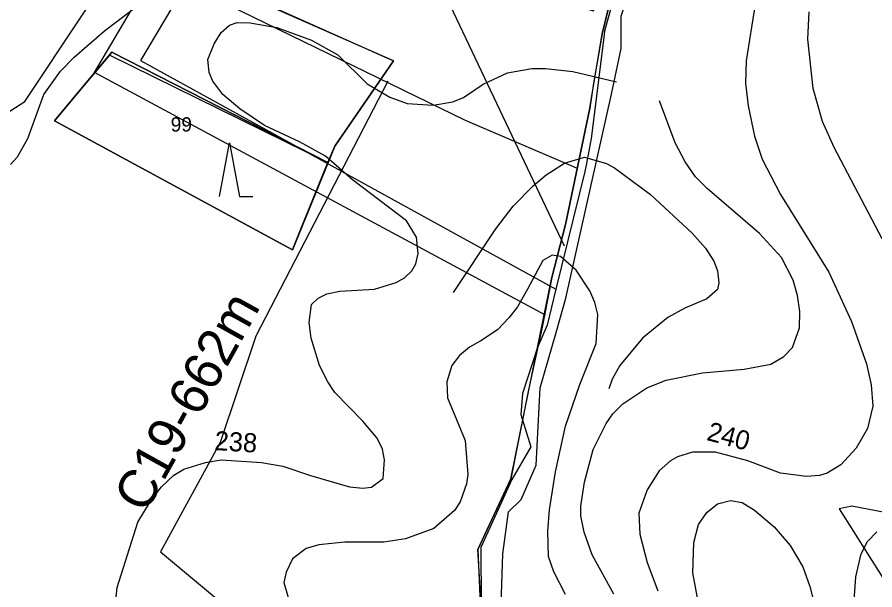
# Model space of a CAD drawing. Extents: x -662500 to -655523, y -1056000 to -1049993.
# Drawn here: x -659685.9 to -659235.8, y -1052866.9 to -1052566.6 of the extents above; entities that cross this region are included whole.
import ezdxf

# ---------------------------------------------------------------- set-up
doc = ezdxf.new("R2010")
doc.units = 0
for name, color, linetype in [('58', 7, 'Continuous'), ('Vrstva 1', 7, 'Continuous'), ('Vrstva 12', 7, 'Continuous'), ('Vrstva 15', 7, 'Continuous'), ('Vrstva 16', 7, 'Continuous'), ('Vrstva 24', 7, 'Continuous'), ('Vrstva 37', 7, 'Continuous'), ('Vrstva 5', 7, 'Continuous'), ('Vrstva 51', 7, 'Continuous'), ('Vrstva 57', 7, 'Continuous'), ('Vrstva 7', 7, 'Continuous')]:
    doc.layers.add(name, color=color, linetype=linetype)

msp = doc.modelspace()

# ---------------------------------------------------------------- linework, layer by layer
at = {"layer": '58'}
msp.add_lwpolyline([(-659328.02, -1052300.49), (-659306.01, -1052350.14), (-659351.19, -1052345.64), (-659376.51, -1052386.45), (-659386.77, -1052453.16), (-659389.91, -1052477.37), (-659350.86, -1052466.04), (-659360.95, -1052515.07), (-659372.04, -1052553.55), (-659377.67, -1052573.87), (-659378, -1052577.29), (-659384.78, -1052630.2), (-659387.27, -1052644.16), (-659388.08, -1052647.48), (-659403.17, -1052709.23), (-659407.79, -1052728.1), (-659412.92, -1052739.74), (-659420.7, -1052763.94), (-659421.56, -1052774.88), (-659416.29, -1052791.84), (-659426.36, -1052809.02), (-659442.52, -1052844.7), (-659442.36, -1052874.55)], dxfattribs=at)
at = {"layer": 'Vrstva 1'}
msp.add_line((-659666.36, -1052620.96), (-659656, -1052608.58), dxfattribs=at)
for points in [[(-659326.1, -1052304.85), (-659306.57, -1052350.72), (-659351.57, -1052346.35), (-659378.02, -1052386.02), (-659390.97, -1052476.36), (-659351.38, -1052464.53), (-659360.53, -1052508.64), (-659373.81, -1052554.38), (-659378.95, -1052575.38), (-659383.52, -1052601.23), (-659385.35, -1052614.38), (-659398.17, -1052675.24), (-659405.34, -1052703.15), (-659410.42, -1052729.16), (-659417.6, -1052762.04), (-659426.9, -1052808.74), (-659444.11, -1052845.81), (-659442.9, -1052874.31)], [(-659656, -1052608.58), (-659636.28, -1052585.02), (-659522.86, -1052642.76), (-659537.13, -1052678.16)], [(-659666.36, -1052620.96), (-659541.43, -1052688.68), (-659537.13, -1052678.16)]]:
    msp.add_lwpolyline(points, dxfattribs=at)
at = {"layer": 'Vrstva 12'}
msp.add_lwpolyline([(-659975.22, -1052363.23), (-659957.91, -1052372.73), (-659920.43, -1052396.6), (-659893.12, -1052405.51), (-659744.12, -1052478.37), (-659614.29, -1052540.87), (-659450.8, -1052620.7), (-659391.97, -1052645.81)], dxfattribs=at)
at = {"layer": 'Vrstva 15'}
msp.add_lwpolyline([(-659491.47, -1052600.22), (-659560.64, -1052733.92), (-659579.45, -1052789.58), (-659610.72, -1052846.89), (-659556.93, -1052891.69), (-659532.56, -1052924.18), (-659546.19, -1053014.6), (-659577.15, -1053106.27), (-659597.46, -1053161.91), (-659614.21, -1053201.5)], dxfattribs=at)
at = {"layer": 'Vrstva 24'}
for points in [[(-659432, -1052926), (-659430.5, -1052919), (-659432.03, -1052911.34), (-659433, -1052906.5), (-659431, -1052848), (-659428, -1052826), (-659421.5, -1052819.5), (-659413.5, -1052801.5), (-659411.5, -1052761), (-659403, -1052732), (-659398, -1052714), (-659374, -1052607), (-659369, -1052583), (-659369, -1052566), (-659365, -1052554), (-659356, -1052547)], [(-659139, -1052880), (-659187, -1052864), (-659206, -1052831), (-659248, -1052823), (-659254.5, -1052824.5), (-659232, -1052860), (-659216, -1052897.5)]]:
    msp.add_lwpolyline(points, dxfattribs=at)
msp.add_lwpolyline([(-659522.86, -1052642.76), (-659636.28, -1052585.02), (-659656, -1052608.58), (-659666.36, -1052620.96), (-659541.43, -1052688.68), (-659537.13, -1052678.16)], close=True, dxfattribs=at)
at = {"layer": 'Vrstva 37'}
msp.add_lwpolyline([(-659725.21, -1052638.68), (-659681.94, -1052610.76), (-659593.13, -1052477.47), (-659512.86, -1052470.64), (-659444.33, -1052545.04), (-659383.41, -1052563.27), (-659346.98, -1052483.53), (-659323.49, -1052406.63), (-659265.71, -1052368.75), (-659265.71, -1052313.92), (-659298.73, -1052302.49), (-659368.75, -1052154.96), (-659417.14, -1052139.58), (-659488.88, -1052161.23), (-659509.37, -1052148.69), (-659509.37, -1052124.63), (-659530.01, -1052053.42), (-659514.64, -1052002.73), (-659551.64, -1051995.89), (-659673.12, -1052221.79), (-659730.97, -1052288.96)], dxfattribs=at)
at = {"layer": 'Vrstva 5'}
for points in [[(-659442.36, -1052874.55), (-659444.11, -1052845.81), (-659426.9, -1052808.74), (-659412.92, -1052739.74), (-659405.34, -1052703.15), (-659398.17, -1052675.24), (-659385.35, -1052614.38), (-659378.95, -1052575.38), (-659373.81, -1052554.38), (-659360.53, -1052508.64), (-659351.38, -1052464.53), (-659390.97, -1052476.36), (-659378.02, -1052386.02), (-659351.57, -1052346.35), (-659306.57, -1052350.72), (-659328.02, -1052300.49)], [(-659931.7, -1052394.49), (-659546.84, -1052563.39), (-659488.42, -1052589.49), (-659519.16, -1052634.21), (-659541.43, -1052688.68), (-659666.36, -1052620.96), (-659637.28, -1052586.47), (-659522.86, -1052642.76), (-659519.16, -1052634.21), (-659488.42, -1052589.49), (-659931.7, -1052394.49)], [(-659579.75, -1052660.56), (-659574.5, -1052632.56), (-659569.25, -1052660.56), (-659562.25, -1052660.56)]]:
    msp.add_lwpolyline(points, dxfattribs=at)
msp.add_lwpolyline([(-659666.36, -1052620.96), (-659636.28, -1052585.02), (-659522.86, -1052642.76), (-659541.43, -1052688.68)], close=True, dxfattribs=at)
at = {"layer": 'Vrstva 51'}
for points in [[(-660169.13, -1053023.13), (-660110.85, -1052940.58), (-660079.74, -1052916.29), (-659950.2, -1052798.66), (-659898.58, -1052720.65), (-659915.89, -1052669.98), (-659910.89, -1052596.38), (-659900.42, -1052552.71), (-659942.19, -1052387.83), (-659921.6, -1052399.48), (-659893.5, -1052409.43), (-659785.78, -1052462.16), (-659600.37, -1052554.27), (-659621.1, -1052589.25), (-659403.17, -1052709.23)], [(-659408.68, -1052722.85), (-659645.22, -1052595.6), (-659623.64, -1052558.85), (-659899.32, -1052423.28), (-659921, -1052417.16), (-659884.97, -1052552.61), (-659896.01, -1052598.65), (-659902.05, -1052660.61), (-659882, -1052722.78), (-659938.73, -1052808.5), (-660070.07, -1052927.77), (-660099.87, -1052951.04), (-660151.35, -1053023.96)]]:
    msp.add_lwpolyline(points, dxfattribs=at)
at = {"layer": 'Vrstva 57'}
msp.add_lwpolyline([(-659618.3, -1052043.89), (-659602.31, -1052104.35), (-659598.67, -1052138.3), (-659592.06, -1052165.06), (-659579.9, -1052186.97), (-659553.68, -1052246.68), (-659542.36, -1052285.96), (-659538.36, -1052313.22), (-659527.2, -1052345.29), (-659508.78, -1052388.91), (-659474.8, -1052526.47), (-659398.9, -1052686.49)], dxfattribs=at)
at = {"layer": 'Vrstva 7'}
for p, q in [((-659640.13, -1052573.76), (-659618.3, -1052557.18)), ((-659298.7, -1052559.85), (-659303.4, -1052589.47)), ((-659271.08, -1052578.07), (-659270.37, -1052563.84)), ((-659578.91, -1052574.61), (-659574.51, -1052570.79)), ((-659574.51, -1052570.79), (-659570.4, -1052569.37)), ((-659570.4, -1052569.37), (-659563.6, -1052569.51)), ((-659563.6, -1052569.51), (-659549.71, -1052572.06)), ((-659549.71, -1052572.06), (-659531.38, -1052578.67)), ((-659656, -1052587.65), (-659640.13, -1052573.76)), ((-659582.45, -1052580.56), (-659578.91, -1052574.61)), ((-659585.85, -1052588.78), (-659582.45, -1052580.56)), ((-659531.38, -1052578.67), (-659517.67, -1052586.43)), ((-659268.23, -1052603.99), (-659271.08, -1052578.07)), ((-659517.67, -1052586.43), (-659502.16, -1052601.57)), ((-659663.08, -1052594.88), (-659656, -1052587.65)), ((-659585.14, -1052595.59), (-659585.85, -1052588.78)), ((-659303.4, -1052589.47), (-659303.69, -1052601.14)), ((-659671.87, -1052607.21), (-659663.08, -1052594.88)), ((-659583.16, -1052600.12), (-659585.14, -1052595.59)), ((-659441.37, -1052601.71), (-659428.55, -1052595.87)), ((-659428.55, -1052595.87), (-659415.74, -1052593.59)), ((-659415.74, -1052593.59), (-659408.62, -1052593.59)), ((-659408.62, -1052593.59), (-659394.38, -1052595.16)), ((-659394.38, -1052595.16), (-659371.45, -1052600.57)), ((-659577.91, -1052607.21), (-659583.16, -1052600.12)), ((-659502.16, -1052601.57), (-659490.35, -1052608.54)), ((-659451.62, -1052608.69), (-659441.37, -1052601.71)), ((-659303.69, -1052601.14), (-659302.4, -1052613.1)), ((-659263.39, -1052621.36), (-659268.23, -1052603.99)), ((-659680.37, -1052630.31), (-659671.87, -1052607.21)), ((-659569.13, -1052614.72), (-659577.91, -1052607.21)), ((-659490.35, -1052608.54), (-659481.23, -1052611.96)), ((-659457.32, -1052610.96), (-659451.62, -1052608.69)), ((-659481.23, -1052611.96), (-659467.57, -1052612.67)), ((-659467.57, -1052612.67), (-659457.32, -1052610.96)), ((-659340.56, -1052632.46), (-659348.92, -1052610.55)), ((-659302.4, -1052613.1), (-659298.99, -1052629.05)), ((-659556.09, -1052623.47), (-659569.13, -1052614.72)), ((-659257.27, -1052635.03), (-659263.39, -1052621.36)), ((-659537.72, -1052631.9), (-659556.09, -1052623.47)), ((-659685.76, -1052639.8), (-659680.37, -1052630.31)), ((-659524.16, -1052639.42), (-659537.72, -1052631.9)), ((-659298.99, -1052629.05), (-659295, -1052641.01)), ((-659335.29, -1052642.43), (-659340.56, -1052632.46)), ((-659232.07, -1052682.87), (-659257.27, -1052635.03)), ((-659689.44, -1052643.91), (-659685.76, -1052639.8)), ((-659509.85, -1052651.97), (-659524.16, -1052639.42)), ((-659398.65, -1052643.14), (-659388.12, -1052640.01)), ((-659388.12, -1052640.01), (-659376.58, -1052643.28)), ((-659408.34, -1052649.26), (-659398.65, -1052643.14)), ((-659376.58, -1052643.28), (-659372.46, -1052645.56)), ((-659329.88, -1052650.4), (-659335.29, -1052642.43)), ((-659295, -1052641.01), (-659285.32, -1052659.52)), ((-659415.17, -1052654.96), (-659408.34, -1052649.26)), ((-659372.46, -1052645.56), (-659353.52, -1052659.52)), ((-659481.52, -1052673.47), (-659509.85, -1052651.97)), ((-659323.9, -1052656.53), (-659329.88, -1052650.4)), ((-659425.56, -1052665.78), (-659415.17, -1052654.96)), ((-659296.28, -1052680.02), (-659323.9, -1052656.53)), ((-659353.52, -1052659.52), (-659331.73, -1052679.88)), ((-659285.32, -1052659.52), (-659259.97, -1052700.24)), ((-659434.68, -1052677.6), (-659425.56, -1052665.78)), ((-659476.39, -1052682.01), (-659481.52, -1052673.47)), ((-659456.89, -1052710.92), (-659434.68, -1052677.6)), ((-659331.73, -1052679.88), (-659324.76, -1052687.71)), ((-659284.75, -1052692.55), (-659296.28, -1052680.02)), ((-659475.54, -1052690.55), (-659476.39, -1052682.01)), ((-659324.76, -1052687.71), (-659320.34, -1052694.54)), ((-659476.68, -1052695.97), (-659475.54, -1052690.55)), ((-659410, -1052694.23), (-659418.06, -1052709.16)), ((-659405.2, -1052691.38), (-659410, -1052694.23)), ((-659400.71, -1052692.18), (-659405.2, -1052691.38)), ((-659392.54, -1052699.29), (-659400.71, -1052692.18)), ((-659320.34, -1052694.54), (-659318.35, -1052699.67)), ((-659278.77, -1052704.51), (-659284.75, -1052692.55)), ((-659478.81, -1052699.67), (-659476.68, -1052695.97)), ((-659385.33, -1052710.11), (-659392.54, -1052699.29)), ((-659486.93, -1052705.79), (-659482.66, -1052703.37)), ((-659482.66, -1052703.37), (-659478.81, -1052699.67)), ((-659318.35, -1052699.67), (-659317.64, -1052705.93)), ((-659259.97, -1052700.24), (-659248.02, -1052726.15)), ((-659498.32, -1052709.21), (-659486.93, -1052705.79)), ((-659317.64, -1052705.93), (-659318.49, -1052709.35)), ((-659276.35, -1052712.48), (-659278.77, -1052704.51)), ((-659527.94, -1052713.91), (-659523.38, -1052711.63)), ((-659523.38, -1052711.63), (-659516.55, -1052710.35)), ((-659516.55, -1052710.35), (-659498.32, -1052709.21)), ((-659418.06, -1052709.16), (-659423.28, -1052718.45)), ((-659382.78, -1052716.27), (-659385.33, -1052710.11)), ((-659318.49, -1052709.35), (-659324.05, -1052714.33)), ((-659275.21, -1052721.02), (-659276.35, -1052712.48)), ((-659532.63, -1052726.72), (-659531.49, -1052717.32)), ((-659531.49, -1052717.32), (-659527.94, -1052713.91)), ((-659381.12, -1052722.46), (-659382.78, -1052716.27)), ((-659324.05, -1052714.33), (-659335.58, -1052719.17)), ((-659423.28, -1052718.45), (-659427.67, -1052724.15)), ((-659335.58, -1052719.17), (-659344.41, -1052724.16)), ((-659275.35, -1052729.57), (-659275.21, -1052721.02)), ((-659427.67, -1052724.15), (-659433.92, -1052730.52)), ((-659382.09, -1052737.75), (-659381.12, -1052722.46)), ((-659344.41, -1052724.16), (-659357.79, -1052734.98)), ((-659248.02, -1052726.15), (-659240.18, -1052748.36)), ((-659531.64, -1052734.98), (-659532.63, -1052726.72)), ((-659433.92, -1052730.52), (-659442.52, -1052736.34)), ((-659279.05, -1052739.82), (-659275.35, -1052729.57)), ((-659527.22, -1052749.22), (-659531.64, -1052734.98)), ((-659357.79, -1052734.98), (-659369.61, -1052749.22)), ((-659448.49, -1052739.68), (-659453.76, -1052744.09)), ((-659442.52, -1052736.34), (-659448.49, -1052739.68)), ((-659390.68, -1052759.18), (-659382.09, -1052737.75)), ((-659283.61, -1052744.52), (-659279.05, -1052739.82)), ((-659453.76, -1052744.09), (-659457.74, -1052749.22)), ((-659304.4, -1052751.21), (-659290.45, -1052748.5)), ((-659290.45, -1052748.5), (-659283.61, -1052744.52)), ((-659240.18, -1052748.36), (-659237.76, -1052759.47)), ((-659522.95, -1052757.76), (-659527.22, -1052749.22)), ((-659457.74, -1052749.22), (-659460.45, -1052757.76)), ((-659369.61, -1052749.22), (-659373.67, -1052756.45)), ((-659345.26, -1052756.9), (-659326.33, -1052753.06)), ((-659326.33, -1052753.06), (-659304.4, -1052751.21)), ((-659519.11, -1052763.45), (-659522.95, -1052757.76)), ((-659460.45, -1052757.76), (-659460.16, -1052766.3)), ((-659373.67, -1052756.45), (-659375.49, -1052761.43)), ((-659355.51, -1052760.89), (-659345.26, -1052756.9)), ((-659398.23, -1052781.11), (-659390.68, -1052759.18)), ((-659368.04, -1052769.43), (-659355.51, -1052760.89)), ((-659237.76, -1052759.47), (-659236.91, -1052770.57)), ((-659504.44, -1052778.4), (-659519.11, -1052763.45)), ((-659460.16, -1052766.3), (-659450.77, -1052788.51)), ((-659373.31, -1052774.56), (-659368.04, -1052769.43)), ((-659236.91, -1052770.57), (-659239.61, -1052782.25)), ((-659376.87, -1052779.69), (-659373.31, -1052774.56)), ((-659496.9, -1052787.37), (-659504.44, -1052778.4)), ((-659383.56, -1052793.35), (-659376.87, -1052779.69)), ((-659403.35, -1052805.03), (-659398.23, -1052781.11)), ((-659239.61, -1052782.25), (-659245.59, -1052792.64)), ((-659494.19, -1052793.07), (-659496.9, -1052787.37)), ((-659450.77, -1052788.51), (-659449.43, -1052806.39)), ((-659493.05, -1052798.76), (-659494.19, -1052793.07)), ((-659388.26, -1052810.44), (-659383.56, -1052793.35)), ((-659245.59, -1052792.64), (-659253.71, -1052801.33)), ((-659339.42, -1052797.2), (-659343.12, -1052799.33)), ((-659331.45, -1052794.64), (-659339.42, -1052797.2)), ((-659319.49, -1052794.78), (-659331.45, -1052794.64)), ((-659302.41, -1052799.33), (-659319.49, -1052794.78)), ((-659598.46, -1052803.63), (-659587.12, -1052800.08)), ((-659587.12, -1052800.08), (-659578.9, -1052798.81)), ((-659578.9, -1052798.81), (-659557.76, -1052800.14)), ((-659557.76, -1052800.14), (-659546.56, -1052802.07)), ((-659546.56, -1052802.07), (-659531.92, -1052806.88)), ((-659493.76, -1052808.45), (-659493.05, -1052798.76)), ((-659343.12, -1052799.33), (-659348.96, -1052804.46)), ((-659285.32, -1052805.74), (-659302.41, -1052799.33)), ((-659253.71, -1052801.33), (-659260.83, -1052805.74)), ((-659610.22, -1052812.84), (-659603.67, -1052806.84)), ((-659603.67, -1052806.84), (-659598.46, -1052803.63)), ((-659531.92, -1052806.88), (-659511.42, -1052812.86)), ((-659449.43, -1052806.39), (-659450.17, -1052811.39)), ((-659406.63, -1052824.96), (-659403.35, -1052805.03)), ((-659348.96, -1052804.46), (-659355.37, -1052814.43)), ((-659271.65, -1052807.45), (-659285.32, -1052805.74)), ((-659264.82, -1052806.88), (-659271.65, -1052807.45)), ((-659260.83, -1052805.74), (-659264.82, -1052806.88)), ((-659500.03, -1052813), (-659493.76, -1052808.45)), ((-659450.17, -1052811.39), (-659453.48, -1052820.79)), ((-659390.11, -1052822.97), (-659388.26, -1052810.44)), ((-659616.03, -1052820.77), (-659610.22, -1052812.84)), ((-659511.42, -1052812.86), (-659504.58, -1052813.57)), ((-659504.58, -1052813.57), (-659500.03, -1052813)), ((-659355.37, -1052814.43), (-659359.64, -1052826.67)), ((-659622.55, -1052831.4), (-659616.03, -1052820.77)), ((-659453.48, -1052820.79), (-659456.32, -1052825.28)), ((-659318.49, -1052821.83), (-659311.52, -1052819.98)), ((-659311.52, -1052819.98), (-659305.39, -1052821.12)), ((-659456.32, -1052825.28), (-659467.28, -1052834.79)), ((-659407.48, -1052836.07), (-659406.63, -1052824.96)), ((-659390.11, -1052828.09), (-659390.11, -1052822.97)), ((-659324.05, -1052826.39), (-659318.49, -1052821.83)), ((-659305.39, -1052821.12), (-659298.99, -1052825.1)), ((-659298.99, -1052825.1), (-659288.74, -1052833.93)), ((-659388.4, -1052836.64), (-659390.11, -1052828.09)), ((-659359.64, -1052826.67), (-659359.21, -1052837.78)), ((-659328.32, -1052832.65), (-659324.05, -1052826.39)), ((-659633.44, -1052865.7), (-659622.55, -1052831.4)), ((-659330.88, -1052842.05), (-659328.32, -1052832.65)), ((-659288.74, -1052833.93), (-659280.19, -1052843.61)), ((-659467.28, -1052834.79), (-659482.09, -1052840.2)), ((-659407.05, -1052849.45), (-659407.48, -1052836.07)), ((-659384.13, -1052848.6), (-659388.4, -1052836.64)), ((-659359.21, -1052837.78), (-659355.37, -1052852.58)), ((-659239.76, -1052841.48), (-659234.77, -1052836.5)), ((-659527.65, -1052843.33), (-659534.2, -1052845.18)), ((-659513.98, -1052841.91), (-659527.65, -1052843.33)), ((-659493.48, -1052841.91), (-659513.98, -1052841.91)), ((-659482.09, -1052840.2), (-659493.48, -1052841.91)), ((-659331.31, -1052858), (-659330.88, -1052842.05)), ((-659243.03, -1052848.03), (-659239.76, -1052841.48)), ((-659534.2, -1052845.18), (-659541.46, -1052850.59)), ((-659280.19, -1052843.61), (-659273.64, -1052854.86)), ((-659541.46, -1052850.59), (-659544.74, -1052857.71)), ((-659404.21, -1052857.43), (-659407.05, -1052849.45)), ((-659372.88, -1052869.1), (-659384.13, -1052848.6)), ((-659245.88, -1052859.99), (-659243.03, -1052848.03)), ((-659355.37, -1052852.58), (-659349.68, -1052867.39)), ((-659273.64, -1052854.86), (-659269.94, -1052865.11)), ((-659544.74, -1052857.71), (-659545.88, -1052863.12)), ((-659398.08, -1052869.39), (-659404.21, -1052857.43)), ((-659328.6, -1052873.09), (-659331.31, -1052858)), ((-659247.3, -1052882.2), (-659245.88, -1052859.99)), ((-659634.74, -1052877.6), (-659633.44, -1052865.7)), ((-659545.88, -1052863.12), (-659542.46, -1052875.08)), ((-659269.94, -1052865.11), (-659266.52, -1052878.5))]:
    msp.add_line(p, q, dxfattribs=at)

# ---------------------------------------------------------------- texts
at = {"layer": 'Vrstva 16'}
msp.add_text('C19-662m', height=20, rotation=60.9495, dxfattribs=at).set_placement((-659618.56, -1052827.45))
at = {"layer": 'Vrstva 24'}
msp.add_text('99', height=7.5, dxfattribs=at).set_placement((-659605.32, -1052626.6))
at = {"layer": 'Vrstva 7'}
for s, rotation, p in [('240', 345.0686, (-659324.57, -1052788.25)), ('238', 356.4, (-659582.53, -1052793.57))]:
    msp.add_text(s, height=10, rotation=rotation, dxfattribs=at).set_placement(p)

doc.saveas('drawing.dxf')
